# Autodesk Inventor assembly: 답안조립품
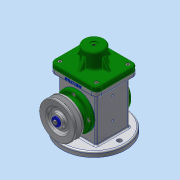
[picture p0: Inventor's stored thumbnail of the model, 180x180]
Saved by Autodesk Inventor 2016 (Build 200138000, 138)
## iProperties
Created: 2018-10
Part Number: 답안조립품
Document SubType Name: Assembly
Designer: MIRAE
Author: MIRAE
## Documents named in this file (18)
- C:\Users\MIRAE\Desktop\481007V1049\답안조립품.iam
- C:\Users\MIRAE\Desktop\481007V1049\본체.ipt
- C:\Users\MIRAE\Desktop\481007V1049\편심축.ipt
- C:\Users\MIRAE\Desktop\481007V1049\베어링 17 x 40 x 12.ipt
- C:\Users\MIRAE\Desktop\481007V1049\뒤커버.ipt
- C:\Users\MIRAE\Desktop\481007V1049\볼트 M4 x 8.ipt
- C:\Users\MIRAE\Desktop\481007V1049\앞커버.ipt
- C:\Users\MIRAE\Desktop\481007V1049\링크.ipt
- C:\Users\MIRAE\Desktop\481007V1049\클레비스 핀 6 x 22.ipt
- 클레비스 핀 6 x 22.ipt
- C:\Users\MIRAE\Desktop\481007V1049\슬라이더.ipt
- C:\Users\MIRAE\Desktop\481007V1049\E-링.ipt
- C:\Users\MIRAE\Desktop\481007V1049\키 4 x 4 x 12.ipt
- C:\Users\MIRAE\Desktop\481007V1049\오일 실 17 30 8.ipt
- C:\Users\MIRAE\Desktop\481007V1049\V-벨트풀리.ipt
- C:\Users\MIRAE\Desktop\481007V1049\와셔 4x16.ipt
- C:\Users\MIRAE\Desktop\481007V1049\볼트 M4 x 10.ipt
- C:\Users\MIRAE\Desktop\481007V1049\덮개.ipt
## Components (2 placed, 2 different names)
1. E-링:1
2. V-벨트풀리:1
